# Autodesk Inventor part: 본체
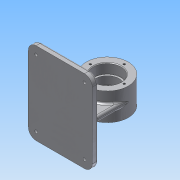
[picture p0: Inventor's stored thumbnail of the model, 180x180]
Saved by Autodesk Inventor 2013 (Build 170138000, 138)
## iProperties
Created: 2019-09
Part Number: 본체
Material: 알루미늄 6061
Document SubType Name: Modeling
Designer: Administrator
Density: 2.71 g/cm^3
Mass: 556.675 g
Surface Area: 495.884 cm^2
Volume: 205.415 cm^3
Author: Administrator
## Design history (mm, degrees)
sketch "스케치1"
  geometry: C1 r 32 at (0, 0); 1 further point
  constraints: 1 centre point, 1 coincident
  dimensions: "d0" = 64 diameter of C1
extrude "돌출1" new body sketch "스케치1" distance "d1" = 21; taper "d2" = 0 deg
hole "구멍1" diameter "d5" = 36; stored, may be unused: countersink angle "d9" = 90 deg, drill point angle "d11" = 118 deg; dims "d3" = 10, "d4" = 10, "d6" = 6, "d7" = 42, "d8" = 15, "d10" = 8
sketch "스케치2"
  geometry: C1 r 21 at (0, 0) reference; 1 further point
  constraints: 1 vertical alignment
  dimensions: "d12" = 26 distance of C1.centre point (0, 26)
hole "구멍2" sketch "스케치2" at (0, 26) diameter "d13" = 3.242; stored, may be unused: countersink angle "d17" = 90 deg, drill point angle "d19" = 118 deg; dims "d14" = 8, "d15" = 42, "d16" = 15, "d18" = 10
fillet "모깎기1" dims "d23" = 0.3
chamfer "모따기1" distance "d24" = 1; stored, may be unused: second distance "d25" = 2, angle "d26" = 45 deg
node "작업 평면1"
sketch "스케치3"
  geometry: L1 (62, 63)-(-36, 63); L2 (-36, 63)-(-36, -63); L3 (-36, -63)-(62, -63); L4 (62, -63)-(62, 63); 1 further point
  constraints: 8 end point, 2 parallel, 1 horizontal, 1 perpendicular
  dimensions: "d28" = 98 distance of L3.end L2.end; "d29" = 126 distance of L2.end L1.end; "d30" = 63 distance from line of point (0, 0) L3; "d31" = 62 distance from line of point (0, 0) L4
extrude "돌출2" join sketch "스케치3" distance "d32" = 9; taper "d33" = 0 deg
fillet "모깎기2" dims "d34" = 12
sketch "스케치4"
  geometry: A1 r 12 centre (-50, -51) between (-62, -51) and (-50, -63) reference; A2 r 12 centre (24, -51) between (24, -63) and (36, -51) reference; A3 r 12 centre (24, 51) between (36, 51) and (24, 63) reference; A4 r 12 centre (-50, 51) between (-50, 63) and (-62, 51) reference; 5 further points
  constraints: 4 coincident
hole "구멍3" sketch "스케치4" at (-50, 51), (24, 51), (24, -51), (-50, -51) diameter "d35" = 4.5; stored, may be unused: countersink angle "d39" = 90 deg, drill point angle "d41" = 0 deg; dims "d36" = 8, "d37" = 8, "d38" = 4.4, "d40" = 10
sketch "스케치5"
  geometry: L1 (-4, -17)-(4, -17); L2 (4, -17)-(4, 17); L3 (4, 17)-(-4, 17); L4 (-4, 17)-(-4, -17); 3 further points
  constraints: 8 end point, 2 midpoint, 2 parallel, 1 horizontal, 1 horizontal alignment, 1 perpendicular, 1 vertical alignment
  dimensions: "d45" = 8 distance of L2.end L3.end; "d47" = 34 distance of L3.end L1.start
extrude "돌출3" join sketch "스케치5" stored distance "d48" = 10; taper "d49" = 0 deg
sketch "스케치6"
  geometry: L1 (-32, -48.033)-(-32, -30.644); C1 r 32 at (0, 0) reference; 1 further point
  constraints: 2 end point, 1 tangent, 1 vertical
feature "리브1" sketch "스케치6" dims "d50" = 1, "d51" = 8, "d52" = 0, "d53" = 0, "d54" = 1, "d55" = 1
sketch "스케치7"
  geometry: L1 (-62, 51)-(-62, -51) reference; 2 further points
  constraints: 1 horizontal alignment, 1 other
  dimensions: "d56" = 10 distance from line of point (-52, 0) L1
feature "엠보싱1" sketch "스케치7" dims "d20" = 40, "d57" = 0.5, "d58" = 0
fillet "모깎기3" dims "d59" = 3
fillet "모깎기4" dims "d60" = 3
fillet "모깎기5" dims "d61" = 3
fillet "모깎기6" dims "d62" = 3
node "솔리드1"
pattern_circular "원형 패턴1" dims angle "d21" = 360 deg
mirror "대칭1"
mirror "대칭2"
other parameters: "d27" = -59
